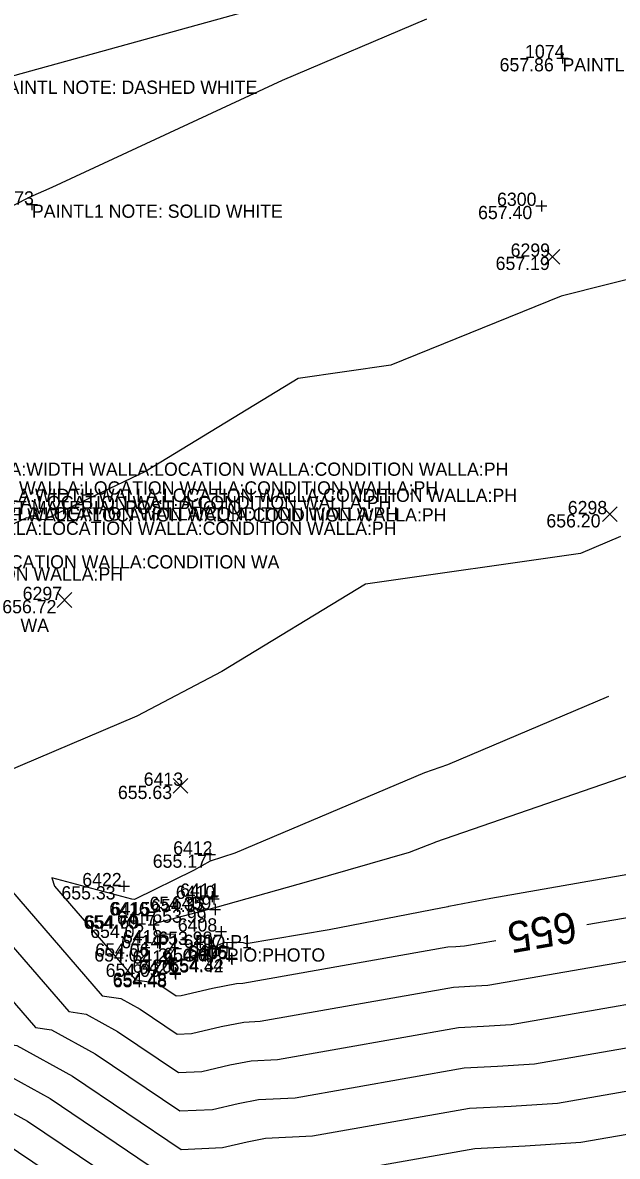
# Model space of a CAD drawing. Extents: x 2129350 to 2137777, y 657588 to 659885.
# Drawn here: x 2132562.6 to 2132616.5, y 658413.1 to 658515.9 of the extents above; entities that cross this region are included whole.
import ezdxf

# ---------------------------------------------------------------- set-up
doc = ezdxf.new("R2010")
doc.units = 0
for name, color, linetype in [('BR_X_SV_Abut_Text', 7, 'Continuous'), ('DT_X_Contour_Major', 7, 'Continuous'), ('DT_X_Contour_Minor', 7, 'Continuous'), ('PV_X_COP', 7, 'Continuous'), ('SV_X_Random_Point', 7, 'Continuous'), ('SV_X_Shot_Marker', 7, 'Continuous'), ('SV_X_Text_Comment', 7, 'Continuous'), ('SV_X_Text_Description', 7, 'Continuous'), ('SV_X_Text_Elevation', 7, 'Continuous'), ('SV_X_Text_Name', 7, 'Continuous')]:
    doc.layers.add(name, color=color, linetype=linetype)

msp = doc.modelspace()

# ---------------------------------------------------------------- linework, layer by layer
at = {"layer": 'DT_X_Contour_Major'}
for points in [[(2132615.67, 658454.8), (2132601.07, 658448.59), (2132599, 658447.88), (2132581.82, 658440.58), (2132579.57, 658439.86), (2132578.07, 658439.01), (2132572.78, 658436.44), (2132572.7, 658436.39), (2132572.48, 658436.43), (2132565.21, 658438.36), (2132565.46, 658437.6), (2132572.8, 658429.12), (2132574.64, 658428.83), (2132575.27, 658428.49), (2132576.48, 658427.67), (2132576.95, 658427.69), (2132579.77, 658428.36), (2132581.95, 658428.79), (2132582.52, 658428.82), (2132601.12, 658432.11), (2132601.84, 658432.14), (2132602.63, 658432.19), (2132605.45, 658432.68)], [(2132613.72, 658434.12), (2132625.77, 658436.22), (2132626.87, 658436.3), (2132628.83, 658436.66), (2132629.9, 658436.77), (2132652.15, 658440.86), (2132653.46, 658441.01), (2132654.9, 658441.2), (2132665.04, 658443.05), (2132666.68, 658443.31), (2132677.99, 658445.31), (2132679.41, 658445.55), (2132680.95, 658445.85), (2132699.89, 658449.22), (2132701.57, 658449.6), (2132703.67, 658449.97), (2132705.45, 658450.46), (2132707.32, 658451.07), (2132712.08, 658451.91)], [(2132488.79, 658419.42), (2132490.99, 658419.99), (2132496.59, 658421.45), (2132504.21, 658423.41), (2132509.82, 658424.88), (2132528.05, 658429.58), (2132537.84, 658432.35), (2132548.05, 658433.04), (2132557.69, 658421.92), (2132558.9, 658421.73), (2132565.06, 658418.35), (2132577.04, 658410.27), (2132578.66, 658410.33)], [(2132586.97, 658411.34), (2132590.41, 658411.51), (2132603.55, 658413.84), (2132608.12, 658414.07), (2132613.16, 658414.39), (2132628.72, 658417.09), (2132633.98, 658417.49), (2132635.26, 658417.73), (2132640.32, 658418.23), (2132654.42, 658420.82), (2132659.58, 658421.41), (2132665.23, 658422.19), (2132671.22, 658423.28), (2132677.2, 658424.21), (2132683.6, 658425.34), (2132685.82, 658425.72)]]:
    msp.add_lwpolyline(points, dxfattribs=at)
at = {"layer": 'DT_X_Contour_Minor'}
for points in [[(2132599.17, 658516.17), (2132586.09, 658510.62), (2132565.21, 658500.91), (2132563.22, 658500.04), (2132563.22, 658500.04), (2132560.18, 658498.49), (2132542.3, 658491.41), (2132538.06, 658489.83), (2132521.06, 658483.18), (2132517.69, 658481.94), (2132517.58, 658481.9), (2132513.3, 658479.66), (2132503.23, 658474.36), (2132488.46, 658465.14)], [(2132628.3, 658495.34), (2132611.38, 658491.08), (2132595.93, 658484.82), (2132587.54, 658483.62), (2132573.71, 658475.19), (2132564.54, 658470.8), (2132562.92, 658470.99), (2132554.66, 658467.07), (2132541.72, 658463.4), (2132537.6, 658458.72), (2132529.55, 658453.9), (2132525.38, 658451.04), (2132520.99, 658449.29), (2132517.8, 658444.44), (2132513.79, 658442.1), (2132505.47, 658434.88), (2132500.3, 658434.41)], [(2132616.75, 658469.3), (2132613.14, 658467.76), (2132593.64, 658464.98), (2132580.63, 658457.05), (2132572.92, 658453.02), (2132557.84, 658446.61), (2132554.86, 658445.77), (2132552.57, 658443.17), (2132556.15, 658443.42), (2132569.78, 658427.68), (2132571.49, 658427.41), (2132573.22, 658426.46), (2132576.59, 658424.19), (2132577.89, 658424.24), (2132580.56, 658424.88), (2132582.61, 658425.28), (2132584.1, 658425.36), (2132601.61, 658428.45), (2132603.09, 658428.53), (2132604.74, 658428.63), (2132626.36, 658432.39)], [(2132617.58, 658447.65), (2132599.99, 658441.58), (2132599.87, 658441.54), (2132599.24, 658441.3), (2132597.6, 658440.66), (2132588.47, 658438.03), (2132579.99, 658435.63), (2132574.83, 658434.28), (2132574.44, 658434.14), (2132574.43, 658434.14), (2132574.43, 658434.14), (2132574.73, 658433.24), (2132576.41, 658433.28), (2132576.43, 658432.69), (2132575.53, 658431.29), (2132575.73, 658430.67), (2132575.82, 658430.56), (2132575.88, 658430.55), (2132575.88, 658430.55), (2132575.97, 658430.57), (2132577.32, 658430.98), (2132580.89, 658432.54), (2132582.57, 658432.5), (2132582.82, 658432.42), (2132590.35, 658433.68), (2132600.64, 658435.67), (2132601.14, 658435.77), (2132601.21, 658435.78), (2132605, 658436.53), (2132625.18, 658440.04)], [(2132493.87, 658427.51), (2132503.81, 658430.07), (2132504, 658430.12), (2132527.9, 658436.28), (2132540.73, 658439.91), (2132554.13, 658440.82), (2132566.75, 658426.24), (2132568.34, 658425.99), (2132571.18, 658424.43), (2132576.71, 658420.71), (2132578.83, 658420.8), (2132581.34, 658421.4), (2132583.28, 658421.78), (2132585.68, 658421.89), (2132602.09, 658424.8), (2132604.35, 658424.91), (2132606.84, 658425.07), (2132626.95, 658428.57)], [(2132494.78, 658425.49), (2132503.94, 658427.85), (2132505.94, 658428.37), (2132527.95, 658434.04), (2132539.77, 658437.39), (2132552.1, 658438.23), (2132563.73, 658424.8), (2132565.2, 658424.57), (2132569.14, 658422.4), (2132576.82, 658417.23), (2132579.77, 658417.35), (2132582.12, 658417.91), (2132583.94, 658418.27), (2132587.26, 658418.43), (2132602.58, 658421.14), (2132605.61, 658421.3), (2132608.95, 658421.51), (2132627.54, 658424.74)], [(2132495.69, 658423.47), (2132504.07, 658425.63), (2132507.88, 658426.63), (2132528, 658431.81), (2132538.8, 658434.87), (2132550.08, 658435.63), (2132560.71, 658423.36), (2132562.05, 658423.15), (2132567.1, 658420.38), (2132576.93, 658413.75), (2132580.7, 658413.91), (2132582.91, 658414.43), (2132584.6, 658414.76), (2132588.84, 658414.97), (2132603.07, 658417.49), (2132606.86, 658417.68), (2132611.06, 658417.95), (2132628.13, 658420.92)], [(2132497.5, 658419.43), (2132504.34, 658421.2), (2132511.76, 658423.13), (2132528.09, 658427.34), (2132536.87, 658429.83), (2132546.03, 658430.45), (2132554.67, 658420.47), (2132555.75, 658420.31), (2132563.02, 658416.32), (2132577.15, 658406.79)], [(2132577.26, 658403.31), (2132560.98, 658414.29), (2132552.61, 658418.88), (2132551.64, 658419.03), (2132544.01, 658427.85), (2132535.91, 658427.3), (2132528.14, 658425.11), (2132513.69, 658421.38), (2132504.47, 658418.98), (2132498.41, 658417.42)]]:
    msp.add_lwpolyline(points, dxfattribs=at)
at = {"layer": 'PV_X_COP'}
msp.add_lwpolyline([(2132174.31, 658404.93), (2132222.67, 658417.74), (2132270.69, 658431.48), (2132318.95, 658444.56), (2132367.41, 658457.86), (2132415.25, 658471.4), (2132463.1, 658484.3), (2132511.79, 658497.66), (2132560.13, 658510.6), (2132608.07, 658523.88), (2132655.96, 658537.1), (2132704.86, 658550.94), (2132752.71, 658564.13), (2132800.76, 658577.31), (2132849.39, 658590.61), (2132897.29, 658603.91), (2132945.59, 658617.44), (2132994.02, 658630.57), (2133042.01, 658643.54), (2133090.19, 658656.9), (2133138.56, 658670.06), (2133186.63, 658683.38), (2133234.84, 658696.93)], dxfattribs=at)
at = {"layer": 'SV_X_Random_Point'}
for p, q in [((2132609.93, 658493.97), (2132611.26, 658495.31)), ((2132609.93, 658495.31), (2132611.26, 658493.97)), ((2132615.12, 658470.65), (2132616.45, 658471.98)), ((2132615.12, 658471.98), (2132616.45, 658470.65)), ((2132565.7, 658462.86), (2132567.03, 658464.2)), ((2132565.7, 658464.2), (2132567.03, 658462.86)), ((2132576.21, 658446.04), (2132577.54, 658447.37)), ((2132576.21, 658447.37), (2132577.54, 658446.04))]:
    msp.add_line(p, q, dxfattribs=at)
at = {"layer": 'SV_X_Shot_Marker'}
for p, q in [((2132611, 658512.64), (2132612, 658512.64)), ((2132611.5, 658513.14), (2132611.5, 658512.14)), ((2132611.5, 658512.64), (2132611.5, 658512.64)), ((2132563.42, 658499.87), (2132563.42, 658498.87)), ((2132562.92, 658499.37), (2132563.92, 658499.37)), ((2132563.42, 658499.37), (2132563.42, 658499.37)), ((2132609.09, 658499.25), (2132610.09, 658499.25)), ((2132609.59, 658499.75), (2132609.59, 658498.75)), ((2132609.59, 658499.25), (2132609.59, 658499.25)), ((2132579.04, 658440.47), (2132580.04, 658440.47)), ((2132579.54, 658440.97), (2132579.54, 658439.97)), ((2132579.54, 658440.47), (2132579.54, 658440.47)), ((2132571.25, 658437.6), (2132572.25, 658437.6)), ((2132571.75, 658438.1), (2132571.75, 658437.1)), ((2132571.75, 658437.6), (2132571.75, 658437.6)), ((2132579.24, 658436.65), (2132580.24, 658436.65)), ((2132579.39, 658436.45), (2132580.39, 658436.45)), ((2132579.74, 658437.15), (2132579.74, 658436.15)), ((2132579.74, 658436.65), (2132579.74, 658436.65)), ((2132579.89, 658436.95), (2132579.89, 658435.95)), ((2132579.89, 658436.45), (2132579.89, 658436.45)), ((2132573.83, 658435.45), (2132573.83, 658434.45)), ((2132573.9, 658435.46), (2132573.9, 658434.46)), ((2132579.52, 658435.49), (2132580.52, 658435.49)), ((2132580.02, 658435.99), (2132580.02, 658434.99)), ((2132580.02, 658435.49), (2132580.02, 658435.49)), ((2132573.33, 658434.95), (2132574.33, 658434.95)), ((2132573.4, 658434.96), (2132574.4, 658434.96)), ((2132573.83, 658434.95), (2132573.83, 658434.95)), ((2132573.9, 658434.96), (2132573.9, 658434.96)), ((2132573.95, 658434.11), (2132574.95, 658434.11)), ((2132574.45, 658434.61), (2132574.45, 658433.61)), ((2132574.45, 658434.11), (2132574.45, 658434.11)), ((2132580.06, 658433.49), (2132581.06, 658433.49)), ((2132580.56, 658433.99), (2132580.56, 658432.99)), ((2132580.56, 658433.49), (2132580.56, 658433.49)), ((2132574.49, 658432.42), (2132575.49, 658432.42)), ((2132574.99, 658432.92), (2132574.99, 658431.92)), ((2132574.99, 658432.42), (2132574.99, 658432.42)), ((2132581.09, 658432.51), (2132581.09, 658431.51)), ((2132575.86, 658431.08), (2132575.86, 658430.08)), ((2132580.59, 658432.01), (2132581.59, 658432.01)), ((2132581.01, 658431.07), (2132582.01, 658431.07)), ((2132581.09, 658432.01), (2132581.09, 658432.01)), ((2132581.51, 658431.57), (2132581.51, 658430.57)), ((2132581.51, 658431.07), (2132581.51, 658431.07)), ((2132581.54, 658431.48), (2132581.54, 658430.48)), ((2132575.36, 658430.58), (2132576.36, 658430.58)), ((2132575.86, 658430.58), (2132575.86, 658430.58)), ((2132576.41, 658430.26), (2132576.41, 658429.26)), ((2132576.42, 658430.14), (2132576.42, 658429.14)), ((2132581.04, 658430.98), (2132582.04, 658430.98)), ((2132581.54, 658430.98), (2132581.54, 658430.98)), ((2132575.91, 658429.76), (2132576.91, 658429.76)), ((2132575.92, 658429.64), (2132576.92, 658429.64)), ((2132576.41, 658429.76), (2132576.41, 658429.76)), ((2132576.42, 658429.64), (2132576.42, 658429.64))]:
    msp.add_line(p, q, dxfattribs=at)

# ---------------------------------------------------------------- texts
at = {"layer": 'BR_X_SV_Abut_Text'}
for s, p in [('WALLA:MATERIAL CONCRETE WALLA:WIDTH WALLA:LOCATION WALLA:CONDITION WALLA:PH', (2132533.21, 658474.79)), ('WALLA:MATERIAL CONCRETE WALLA:WIDTH WALLA:LOCATION WALLA:CONDITION WALLA:PH', (2132526.85, 658473.09)), ('WALLA:MATERIAL CONCRETE WALLA:WIDTH WALLA:LOCATION WALLA:CONDITION WALLA:PH', (2132534, 658472.43)), ('WALLA:MATERIAL CONCRETE WALLA:WIDTH WALLA:LOCATION WALLA:CONDITION WALLA:PH', (2132522.61, 658471.77)), ('WALLA:MATERIAL CONCRETE WALLA:WIDTH WALLA:LOCATION WALLA:CONDITION WALLA:PH', (2132523.21, 658470.74)), ('WALLA:MATERIAL CONCRETE WALLA:WIDTH WALLA:LOCATION WALLA:CONDITION WALLA:PH', (2132527.6, 658470.65)), ('WALLA:MATERIAL CONCRETE WALLA:WIDTH WALLA:LOCATION WALLA:CONDITION WALLA:PH', (2132523.08, 658469.44)), ('WIDTH WALLA:MATERIAL CONCRETE WALLA:WIDTH WALLA:LOCATION WALLA:CONDITION WA', (2132512.29, 658466.39)), ('WALLA:MATERIAL CONCRETE WALLA:WIDTH WALLA:LOCATION WALLA:CONDITION WALLA:PH', (2132498.29, 658465.29)), ('WIDTH WALLA:MATERIAL CONCRETE WALLA:WIDTH WALLA:LOCATION WALLA:CONDITION WA', (2132491.41, 658460.64))]:
    msp.add_text(s, height=1.2, dxfattribs=at).set_placement(p)
at = {"layer": 'DT_X_Contour_Major'}
msp.add_text('655', height=2.8, rotation=189.8614, dxfattribs=at).set_placement((2132612.5, 658435.33))
at = {"layer": 'SV_X_Text_Comment'}
for s, p in [('PAINTL1 NOTE: SOLID WHITE', (2132611.5, 658511.44)), ('PAINTL NOTE: DASHED WHITE', (2132560.13, 658509.4)), ('PAINTL1 NOTE: SOLID WHITE', (2132563.42, 658498.17)), ('BRIDGE PILLAR POST:USE PILLAR POST:SIZE POST:MATERIAL POST:PHOTO', (2132522.65, 658471.31)), ('24 CMP PIO:PHOTO', (2132574.83, 658430.77))]:
    msp.add_text(s, height=1.2, dxfattribs=at).set_placement(p)
at = {"layer": 'SV_X_Text_Description'}
msp.add_text('P1= PIO:P1', height=1.2, dxfattribs=at).set_placement((2132574.83, 658431.97))
at = {"layer": 'SV_X_Text_Elevation'}
for s, p in [('657.86', (2132605.8, 658511.44)), ('657.40', (2132603.85, 658498.05)), ('657.19', (2132605.44, 658493.44)), ('656.20', (2132610.04, 658470.11)), ('656.72', (2132560.73, 658462.33)), ('655.63', (2132571.21, 658445.5)), ('655.17', (2132574.37, 658439.27)), ('655.33', (2132566.09, 658436.4)), ('654.35', (2132574.07, 658435.45)), ('654.33', (2132574.22, 658435.25)), ('653.99', (2132574.33, 658434.29)), ('654.70', (2132568.1, 658433.75)), ('654.69', (2132568.22, 658433.76)), ('654.02', (2132568.7, 658432.91)), ('653.98', (2132574.87, 658432.29)), ('654.06', (2132569.16, 658431.22)), ('654.02', (2132569.07, 658430.77)), ('654.07', (2132575.32, 658430.81)), ('654.34', (2132575.85, 658429.87)), ('654.03', (2132570.1, 658429.38)), ('654.42', (2132575.89, 658429.78)), ('654.48', (2132570.74, 658428.56)), ('654.48', (2132570.75, 658428.44))]:
    msp.add_text(s, height=1.2, dxfattribs=at).set_placement(p)
at = {"layer": 'SV_X_Text_Name'}
for s, p in [('1074', (2132608.11, 658512.64)), ('1073', (2132560.03, 658499.37)), ('6300', (2132605.57, 658499.25)), ('6299', (2132606.8, 658494.64)), ('6298', (2132611.98, 658471.31)), ('6297', (2132562.58, 658463.53)), ('6413', (2132573.55, 658446.7)), ('6412', (2132576.22, 658440.47)), ('6422', (2132567.98, 658437.6)), ('6410', (2132576.46, 658436.45)), ('6411', (2132576.85, 658436.65)), ('6416', (2132570.43, 658434.95)), ('6415', (2132570.58, 658434.96)), ('6409', (2132576.1, 658435.49)), ('6417', (2132571.13, 658434.11)), ('6408', (2132576.64, 658433.49)), ('6414', (2132571.51, 658431.97)), ('6418', (2132571.66, 658432.42)), ('6407', (2132577.17, 658432.01)), ('6406', (2132577.52, 658431.07)), ('6405', (2132577.62, 658430.98)), ('6419', (2132572.53, 658430.58)), ('6420', (2132572.53, 658429.76)), ('6421', (2132573.08, 658429.64))]:
    msp.add_text(s, height=1.2, dxfattribs=at).set_placement(p)

doc.saveas('drawing.dxf')
